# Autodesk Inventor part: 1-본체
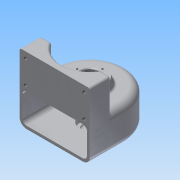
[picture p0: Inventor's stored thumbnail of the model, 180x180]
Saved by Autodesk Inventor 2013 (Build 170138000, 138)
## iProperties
Created: 2015-02
Part Number: 1-본체
Material: 알루미늄 6061
Document SubType Name: Modeling
Designer: Administrator
Density: 2.40731 g/cm^3
Mass: 511.027 g
Surface Area: 707.302 cm^2
Volume: 212.281 cm^3
Author: Administrator
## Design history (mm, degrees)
sketch "스케치1" dims "d0" = 50
  geometry: L1 (-50, 0)-(50, 0); L2 (50, 0)-(50, -50); L3 (50, -50)-(-50, -50); L4 (-50, -50)-(-50, 0); 2 further points
  constraints: 8 end point, 2 parallel, 2 vertical, 1 coincident, 1 horizontal, 1 horizontal alignment, 1 perpendicular, 2 other
  dimensions: "d2" = 50 distance of L1.end L2.end
extrude "돌출1" new body sketch "스케치1" distance "d3" = 50; taper "d4" = 0 deg
fillet "모깎기1" dims "d5" = 10
feature "쉘1" dims "d6" = 4
node "작업 평면1"
sketch "스케치2"
  geometry: L1 (40, -50)-(-40, -50) reference; L2 (-50, -50)-(50, -50); L3 (-50, -50)-(-50, -20); L4 (50, -50)-(50, -20); L5 (-50, -20)-(-34.641, -20); L6 (34.641, -20)-(50, -20); A1 r 40 centre (0, 0) between (-34.641, -20) and (34.641, -20); 1 further point
  constraints: 10 end point, 2 collinear, 2 parallel, 2 perpendicular, 2 point on circle, 1 centre point, 1 coincident
  dimensions: "d10" = 30 distance of L2.start L3.end; "d12" = 40 radius of A1
extrude "돌출2" join sketch "스케치2" stored distance "d13" = 50; taper "d14" = 0 deg
sketch "스케치3"
  geometry: C1 r 25 at (0, 0); A1 r 40 centre (0, 0) between (-34.641, -20) and (34.641, -20) reference
  constraints: 1 centre point, 1 coincident
  dimensions: "d15" = 50 diameter of C1
extrude "돌출3" join sketch "스케치3" distance "d17" = 10; taper "d18" = -20 deg
sketch "스케치4"
  geometry: C1 r 20 at (0, 0); A1 r 40 centre (0, 0) between (40, 0) and (-40, 0) reference
  constraints: 1 centre point, 1 coincident
  dimensions: "d19" = 40 diameter of C1
extrude "돌출4" join sketch "스케치4" distance "d21" = 9; taper "d22" = 0 deg
node "작업 평면2"
sketch "스케치5"
  geometry: L1 (40, -50)-(-40, -50) reference; 2 further points
  constraints: 1 vertical alignment, 1 other
  dimensions: "d23" = 25 distance from line of point (0, -25) L1
feature "엠보싱1" sketch "스케치5" dims "d0" = 50, "d2" = 50, "d24" = 0.5, "d25" = 0
hole "구멍1" diameter "d28" = 20; stored, may be unused: countersink angle "d32" = 90 deg, drill point angle "d34" = 0 deg; dims "d29" = 6, "d30" = 28, "d31" = 10, "d33" = 14, "d44" = 10, "d45" = 10
hole "구멍2" diameter "d37" = 20; stored, may be unused: countersink angle "d41" = 90 deg, drill point angle "d43" = 0 deg; dims "d35" = 10, "d36" = 10, "d38" = 6, "d39" = 28, "d40" = 8, "d42" = 10
sketch "스케치6"
  geometry: C1 r 14 at (0, 0) reference; C2 r 21.36 at (0, 0) reference; A1 r 18 centre (0, 0) between (0, 18) and (-18, 0); 2 further points
  constraints: 4 point on circle, 2 horizontal alignment, 2 vertical alignment, 1 centre point, 1 coincident
  dimensions: "d46" = 36 diameter of A1
hole "구멍3" sketch "스케치6" at (0, 18), (-18, 0), (0, -18), (18, 0) diameter "d48" = 2.459; stored, may be unused: countersink angle "d52" = 90 deg, drill point angle "d54" = 118 deg; dims "d49" = 6, "d50" = 28, "d51" = 8, "d53" = 9
sketch "스케치7"
  geometry: L1 (90, 95)-(90, 10) reference; L2 (-10, 95)-(90, 95) reference; L3 (-1.75, 86)-(81.75, 86); L4 (81.75, 86)-(81.75, 53); L5 (81.75, 53)-(-1.75, 53); L6 (-1.75, 53)-(-1.75, 86); 5 further points
  constraints: 8 end point, 4 coincident, 2 parallel, 1 horizontal, 1 perpendicular
  dimensions: "d55" = 33 distance of L3.end L4.end; "d57" = 83.5 distance of L3.start L3.end; "d58" = 9 distance between parallel lines of L3 L2; "d59" = 8.25 distance between parallel lines of L1 L4
hole "구멍4" sketch "스케치7" at (-1.75, 86), (-1.75, 53), (81.75, 53), (81.75, 86) diameter "d60" = 5.134; stored, may be unused: countersink angle "d64" = 90 deg, drill point angle "d66" = 118 deg; dims "d61" = 10, "d62" = 28, "d63" = 8, "d65" = 13
chamfer "모따기1" distance "d67" = 1; stored, may be unused: second distance "d68" = 2, angle "d69" = 45 deg
fillet "모깎기2" dims "d70" = 0.3
fillet "모깎기3" dims "d71" = 3
node "솔리드1"
other parameters: "d7" = 45
